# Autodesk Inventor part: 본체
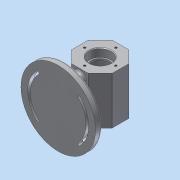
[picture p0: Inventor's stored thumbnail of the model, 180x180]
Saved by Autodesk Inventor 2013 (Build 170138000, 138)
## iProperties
Created: 2017-06
Part Number: 본체
Material: 알루미늄 6061
Document SubType Name: Modeling
Designer: dgall
Density: 2.71 g/cm^3
Mass: 562.521 g
Surface Area: 565.5 cm^2
Volume: 207.572 cm^3
Author: dgall
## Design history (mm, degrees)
sketch "스케치1" dims "d0" = 60
  geometry: L1 (12.426, 30)-(30, 12.426); L2 (30, 12.426)-(30, -12.426); L3 (30, -12.426)-(12.426, -30); L4 (12.426, -30)-(-12.426, -30); L5 (-12.426, -30)-(-30, -12.426); L6 (-30, -12.426)-(-30, 12.426); L7 (-30, 12.426)-(-12.426, 30); L8 (-12.426, 30)-(12.426, 30); 4 further points
  constraints: 16 end point, 2 coincident, 2 vertical alignment, 1 midpoint, 19 other
extrude "돌출1" new body sketch "스케치1" stored distance "d1" = 70; taper "d2" = 0 deg
sketch "스케치2"
  geometry: L1 (30, -35)-(-30, -35) reference; L2 (-30, -35)-(-30, 35) reference; L3 (-30, 35)-(30, 35) reference; L4 (30, 35)-(30, -35) reference; L5 (0, -35)-(16, -35); L6 (16, -35)-(16, -23); L7 (16, -23)-(14, -23); L8 (14, -23)-(14, -20); L9 (14, -20)-(25, -20); L10 (25, -20)-(25, 20); L11 (25, 20)-(14, 20); L12 (14, 20)-(14, 23); L13 (14, 23)-(16, 23); L14 (16, 23)-(16, 35); L15 (16, 35)-(0, 35); L16 (0, 35)-(0, -35)
  constraints: 24 end point, 3 horizontal, 3 parallel, 3 perpendicular, 2 collinear, 2 midpoint, 2 point on line, 2 vertical alignment
  dimensions: "d6" = 12 distance of L5.end L6.end; "d7" = 40 distance of L9.end L10.end; "d9" = 12 distance of L13.end L14.end; "d10" = 32 diameter of L14 L16; "d11" = 50 diameter of L10 L16; "d12" = 28 diameter of L12 L16
revolve "회전1" sketch "스케치2" stored, may be unused: angle "d13" = 90 deg
node "작업 평면1"
sketch "스케치3"
  geometry: C1 r 55 at (0, 0); 1 further point
  constraints: 1 centre point, 1 coincident
  dimensions: "d15" = 110 diameter of C1
extrude "돌출2" join sketch "스케치3" distance "d16" = 10; taper "d17" = 0 deg
sketch "스케치4"
  geometry: L1 (-55, 0)-(0, 0); L2 (0, 0)-(-38.891, -38.891); L3 (-30.406, 30.406)-(0, 0); A1 r 55 centre (0, 0) between (-55, 0) and (-38.891, -38.891) reference; A2 r 43 centre (0, 0) between (-30.406, -30.406) and (-30.406, 30.406); A3 r 48 centre (0, 0) between (-33.941, 33.941) and (-33.941, -33.941); A4 r 38 centre (0, 0) between (-26.87, 26.87) and (-26.87, -26.87); A5 r 5 centre (-30.406, -30.406) between (-33.941, -33.941) and (-26.87, -26.87); A6 r 5 centre (-30.406, 30.406) between (-26.87, 26.87) and (-33.941, 33.941)
  constraints: 12 point on circle, 6 end point, 5 centre point, 4 coincident, 3 point on line, 1 horizontal
  dimensions: "d18" = 86 diameter of A2; "d19" = 96 diameter of A3; "d20" = 76 diameter of A4; "d21" = 45 deg angle of L1 L2; "d23" = 90 deg angle of L2 L3
extrude "돌출3" cut sketch "스케치4" distance "d24" = 3; taper "d25" = 0 deg
sketch "스케치5"
  geometry: A1 r 38 centre (0, 0) between (-26.87, 26.87) and (-26.87, -26.87) reference; A2 r 5 centre (-30.406, 30.406) between (-26.87, 26.87) and (-33.941, 33.941) reference; A3 r 48 centre (0, 0) between (-33.941, 33.941) and (-33.941, -33.941) reference; A4 r 5 centre (-30.406, -30.406) between (-33.941, -33.941) and (-26.87, -26.87) reference; A5 r 45 centre (0, 0) between (-31.82, 31.82) and (-31.82, -31.82); A6 r 2 centre (-30.406, 30.406) between (-28.991, 28.991) and (-31.82, 31.82); A7 r 41 centre (0, 0) between (-28.991, 28.991) and (-28.991, -28.991); A8 r 2 centre (-30.406, -30.406) between (-31.82, -31.82) and (-28.991, -28.991)
  constraints: 8 point on circle, 4 centre point, 3 other
  dimensions: "d26" = 3 radial gap between concentric circles of A3 A5
extrude "돌출4" cut sketch "스케치5" stored distance "d27" = 3; taper "d28" = 0 deg
sketch "스케치6"
  geometry: L1 (16, -35)-(16, -23) reference; L2 (16, -23)-(14, -23) reference; L3 (14, -23)-(14, -20) reference; L4 (14, -20)-(25, -20) reference; L5 (25, -20)-(25, 20) reference; L6 (25, 20)-(14, 20) reference; L7 (14, 20)-(14, 23) reference; L8 (14, 23)-(16, 23) reference; L9 (16, 23)-(16, 35) reference; L10 (16, 35)-(30, 35) reference; L11 (30, 35)-(30, -35) reference; L12 (30, -35)-(16, -35) reference; L13 (-16, -23)-(-16, -35) reference; L14 (-16, -35)-(-30, -35) reference; L15 (-30, -35)-(-30, 35) reference; L16 (-30, 35)-(-16, 35) reference; L17 (-16, 35)-(-16, 23) reference; L18 (-16, 23)-(-14, 23) reference; L19 (-14, 23)-(-14, 20) reference; L20 (-14, 20)-(-25, 20) reference; L21 (-25, 20)-(-25, -20) reference; L22 (-25, -20)-(-14, -20) reference; L23 (-14, -20)-(-14, -23) reference; L24 (-14, -23)-(-16, -23) reference; L25 (-62, 55)-(-52, 55) reference; L26 (-52, 55)-(-52, -55) reference; L27 (-52, -55)-(-62, -55) reference; L28 (-62, -55)-(-62, 55) reference; L29 (-30, 29)-(-52, 29); L30 (-30, -29)-(-52, -29); 1 further point
  constraints: 4 end point, 4 point on line, 2 perpendicular
  dimensions: "d29" = 58 distance between parallel lines of L30 L29; "d30" = 29 distance from line of L30 point (0, 0)
extrude "돌출5" join sketch "스케치6" stored distance "d31" = 10; taper "d32" = 0 deg
fillet "모깎기1" dims "d33" = 1
fillet "모깎기2" dims "d34" = 5
fillet "모깎기3" dims "d35" = 5
fillet "모깎기4" dims "d36" = 3
chamfer "모따기1" distance "d37" = 1; stored, may be unused: second distance "d38" = 2, angle "d39" = 45 deg
fillet "모깎기5" dims "d40" = 0.3
fillet "모깎기6" dims "d41" = 3
sketch "스케치7" dims "d42" = 46
  geometry: C1 r 17 at (0, 0) reference; 2 further points
  constraints: 2 vertical alignment, 1 coincident, 2 other
hole "구멍1" sketch "스케치7" at (0, 23) diameter "d43" = 3.242; stored, may be unused: countersink angle "d47" = 90 deg, drill point angle "d49" = 118 deg; dims "d44" = 8, "d45" = 4, "d46" = 2, "d48" = 10
sketch "스케치8"
  geometry: L1 (-24.024, 70)-(0, 70) reference; L2 (0, 0)-(-24.024, 0) reference; C1 r 8 at (-12.012, 35); 2 further points
  constraints: 1 centre point, 1 midpoint, 1 vertical alignment
  dimensions: "d53" = 35 distance from line of L2 C1.centre; "d54" = 16 diameter of C1
extrude "돌출6" join sketch "스케치8" distance "d55" = 7; taper "d56" = 0 deg
sketch "스케치9"
  geometry: C1 r 8 at (0, 0) reference
hole "구멍2" sketch "스케치9" at (0, 0) diameter "d57" = 8; stored, may be unused: countersink angle "d61" = 90 deg, drill point angle "d63" = 118 deg; dims "d58" = 8, "d59" = 4, "d60" = 2, "d62" = 10
chamfer "모따기2" distance "d64" = 1; stored, may be unused: second distance "d65" = 2, angle "d66" = 45 deg
fillet "모깎기7" dims "d67" = 3
sketch "스케치10"
  geometry: L1 (42.012, 0)-(42.012, 70) reference; L2 (24.731, 70)-(41.719, 70) reference; 2 further points
  constraints: 1 other
  dimensions: "d68" = 30 distance from line of point (12.012, 35) L1; "d69" = 35 distance from line of L2 point (12.012, 35)
feature "엠보싱1" sketch "스케치10" dims "d6" = 12, "d7" = 40, "d9" = 12, "d10" = 32, "d11" = 50, "d12" = 28, "d70" = 0.5, "d71" = 0
node "솔리드1"
mirror "대칭1"
pattern_circular "원형 패턴1" dims angle "d51" = 360 deg
mirror "대칭2"
node "절단 모서리 투영1"
node "절단 모서리 투영2"
other parameters: "d14" = -62
